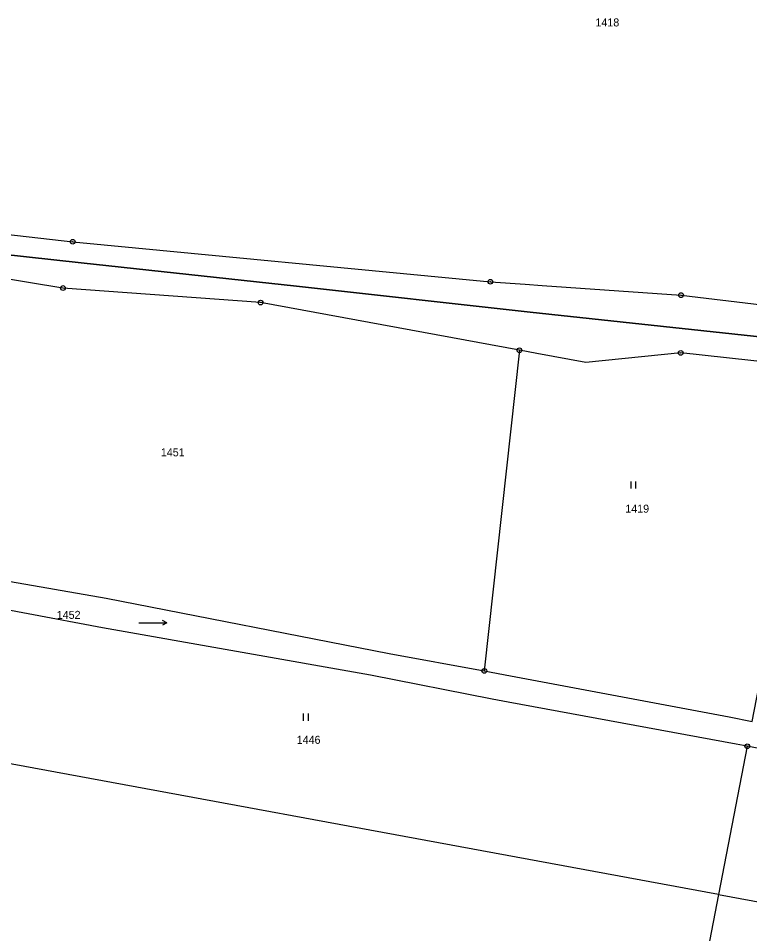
# Model space of a CAD drawing. Extents: x -872229 to -869198, y -1075981 to -1074329.
# Drawn here: x -870924.3 to -870769, y -1075586.7 to -1075392.2 of the extents above; entities that cross this region are included whole.
import ezdxf

# ---------------------------------------------------------------- set-up
doc = ezdxf.new("R2010")
doc.units = 0
doc.header["$LTSCALE"] = 0.68
for name, color, linetype, lineweight in [('1', 7, 'Continuous', 25), ('3', 7, 'Continuous', 25), ('6', 7, 'Continuous', 25), ('8', 7, 'Continuous', 25)]:
    doc.layers.add(name, color=color, linetype=linetype, lineweight=lineweight)
doc.layers.add('2', color=7, linetype='Continuous')

msp = doc.modelspace()

# ---------------------------------------------------------------- linework, layer by layer
at = {"layer": '1'}
msp.add_line((-870817.87, -1075462.75), (-870825.33, -1075530.87), dxfattribs=at)
for points in [[(-870949.31, -1075435.5), (-870912.76, -1075439.69), (-870824.05, -1075448.17), (-870816.69, -1075448.69), (-870813.04, -1075448.95), (-870783.54, -1075451.03), (-870689.55, -1075462.28), (-870596.02, -1075472.9), (-870575.95, -1075474.7)], [(-870817.87, -1075462.75), (-870872.87, -1075452.61), (-870914.84, -1075449.51), (-870944.51, -1075444.65)], [(-870753.84, -1075466.53), (-870783.62, -1075463.3), (-870803.76, -1075465.35), (-870814.2, -1075463.42), (-870817.87, -1075462.75)], [(-870825.33, -1075530.87), (-870819.8, -1075531.88), (-870773.33, -1075540.65), (-870768.45, -1075541.58), (-870753.84, -1075466.53)], [(-870955.2, -1075508.1), (-870936.99, -1075509.94), (-870905.68, -1075515.44), (-870845.51, -1075527.2), (-870825.33, -1075530.87)], [(-870769.48, -1075546.88), (-870771.86, -1075546.41), (-870820.28, -1075537.54), (-870823.66, -1075536.9), (-870849.48, -1075531.79), (-870906.42, -1075521.68), (-870938.07, -1075515.76), (-870962.39, -1075513.2), (-870967.23, -1075543.73)], [(-870775.56, -1075578.36), (-870961.39, -1075544.07), (-870967.23, -1075543.73)], [(-870769.48, -1075546.88), (-870775.56, -1075578.36), (-870723.44, -1075587.98), (-870658.76, -1075599.92), (-870633.02, -1075568.68)], [(-870633.02, -1075568.68), (-870643.23, -1075569.87), (-870653.67, -1075568.67), (-870711.88, -1075558.28), (-870769.48, -1075546.88)], [(-870775.56, -1075578.36), (-870796.43, -1075686.4), (-870817.54, -1075795.72)]]:
    msp.add_lwpolyline(points, dxfattribs=at)
at = {"layer": '3'}
for p, q in [((-870794.161, -1075492.14), (-870794.161, -1075490.64)), ((-870793.16, -1075492.14), (-870793.16, -1075490.64)), ((-870892.743, -1075520.669), (-870893.72, -1075521.17)), ((-870863.711, -1075541.45), (-870863.711, -1075539.95)), ((-870862.71, -1075541.45), (-870862.71, -1075539.95))]:
    msp.add_line(p, q, dxfattribs=at)
msp.add_lwpolyline([(-870898.743, -1075520.669), (-870892.743, -1075520.669), (-870893.72, -1075520.167)], dxfattribs=at)
at = {"layer": '6', "lineweight": 35}
msp.add_line((-870910.94, -1075444.16), (-870865.22, -1075449.1), dxfattribs=at)
for points in [[(-871015.95, -1075430.68), (-870979.48, -1075436.37), (-870951.66, -1075439.69), (-870910.94, -1075444.16)], [(-870865.22, -1075449.1), (-870815.6, -1075454.63), (-870759.62, -1075460.64)]]:
    msp.add_lwpolyline(points, dxfattribs=at)
at = {"layer": '8'}
for centre, radius in [((-870912.76, -1075439.6899), 0.5), ((-870912.76, -1075439.6899), 0.0303), ((-870824.05, -1075448.1699), 0.5), ((-870914.84, -1075449.5099), 0.5), ((-870914.84, -1075449.5099), 0.0303), ((-870824.05, -1075448.1699), 0.0303), ((-870783.54, -1075451.0299), 0.5), ((-870783.54, -1075451.0299), 0.0303), ((-870872.87, -1075452.6099), 0.5), ((-870872.87, -1075452.6099), 0.0303), ((-870817.87, -1075462.7499), 0.5), ((-870817.87, -1075462.7499), 0.0303), ((-870783.62, -1075463.2999), 0.5), ((-870783.62, -1075463.2999), 0.0303), ((-870825.33, -1075530.8699), 0.5), ((-870825.33, -1075530.8699), 0.0303), ((-870769.48, -1075546.8799), 0.5), ((-870769.48, -1075546.8799), 0.0303)]:
    msp.add_circle(centre, radius, dxfattribs=at)

# ---------------------------------------------------------------- texts
at = {"layer": '2'}
for s, p in [('1418', (-870801.73, -1075393.93)), ('1451', (-870894.04, -1075485.27)), ('1419', (-870795.39, -1075497.25)), ('1452', (-870916.15, -1075519.81)), ('1446', (-870865.18, -1075546.36))]:
    msp.add_text(s, height=1.7, dxfattribs=at).set_placement(p)

doc.saveas('drawing.dxf')
